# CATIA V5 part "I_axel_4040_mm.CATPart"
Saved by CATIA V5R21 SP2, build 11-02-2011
Part number: Axel_4040_mm
Bounding box of the stored display mesh (mm): x -20 to 20, y -30 to 30, z 0 to 40
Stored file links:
  \\ariel.ad.iei.liu.se\LAB_DELMIA\A1_LAB_INTRO_2011\LAB_INTRO_DATA_2011\I_axel_4040_mm.CATPart
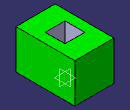
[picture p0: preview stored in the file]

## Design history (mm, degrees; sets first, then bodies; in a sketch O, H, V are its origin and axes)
Body1 (main body)
  Sketch1 on xy-plane, origin (0, 0, 0), H (1, 0, 0), V (0, 1, 0)
    line L1 (-20, -30) -> (20, -30)
    line L2 (20, -30) -> (20, 30)
    line L3 (20, 30) -> (-20, 30)
    line L4 (-20, 30) -> (-20, -30)
    horizontal: L1 H, L3 H
    vertical: L2 V, L4 V
  Pad1: profile Sketch1, direction (0, 0, 1), length 40
  Sketch2 on xy-plane, origin (0, 0, 0), H (1, 0, 0), V (0, 1, 0)
    line L1 (-10.1, 10.1) -> (10.1, 10.1)
    line L2 (10.1, 10.1) -> (10.1, -10.1)
    line L3 (10.1, -10.1) -> (-10.1, -10.1)
    line L4 (-10.1, -10.1) -> (-10.1, 10.1)
    horizontal: L1 H, L3 H
    vertical: L2 V, L4 V
  Pocket1: profile Sketch2, direction (0, 0, 1), length 40, opposite side length -20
